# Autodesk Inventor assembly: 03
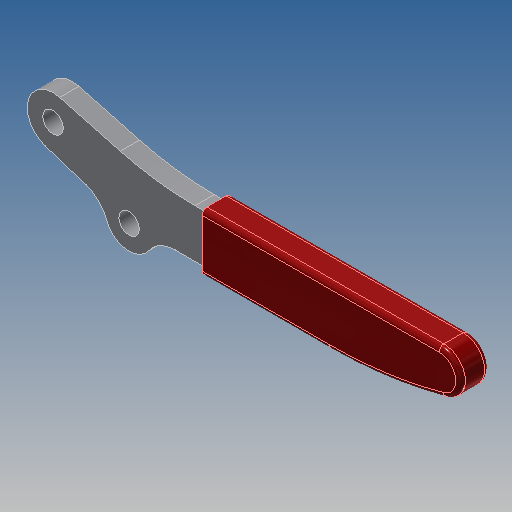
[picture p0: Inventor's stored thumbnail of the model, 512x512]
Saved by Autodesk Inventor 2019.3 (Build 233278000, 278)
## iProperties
Created: 2012-09
Part Number: 03
Material: Ogólny
Document SubType Name: Assembly
Designer: CADENGINEERING4
Author: CADENGINEERING4
Revision Number: ÈÎºÎ
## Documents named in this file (3)
- E:\STRONA\Horizontal toggle clamp\CH-203-FL\03.iam
- E:\STRONA\Horizontal toggle clamp\CH-203-FL\203-F-03-02.ipt
- E:\STRONA\Horizontal toggle clamp\CH-203-FL\203-F-03.ipt
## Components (2 placed, 2 different names)
1. 203-F-03-02_15
2. 203-F-03_16
